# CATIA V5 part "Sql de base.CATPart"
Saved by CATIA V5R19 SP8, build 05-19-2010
Part number: Sql de base
Publications: "Origine", "A bielle", "B bielle", "Longueur Bielle", "entraxe", "D bielle", "C bielle", "Z chape verin para", "Y chape verin para", "Z chape verin frein", "Y chape verin frein", "B verin para", "B verin frein", "A verin frein", "A verin para", "Axe sabot", "Plan xy", "Plan yz", "Plan zx", "Cremaillere", "Z cremaillere", "Largeur bielle", "X Sabot", "Y Sabot", "X Cremaillere", "Y Cremaillere"
Bounding box of the stored display mesh (mm): x 0 to 0, y -950 to 470, z -1670 to 0
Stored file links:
  G:\EU_thinkMotion\CFAO_2010\MMS_groupe3\MMS_groupe3\rdalborgo\rdalborgo\Sql de base.CATPart
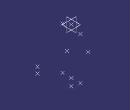
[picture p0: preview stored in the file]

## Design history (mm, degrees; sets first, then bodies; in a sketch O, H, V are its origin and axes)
Parameters
  entraxe = 500 mm
  `Longueur Bielle` = 1200 mm
  `Z chape verin para` = -425 mm
  `Y chape verin para` = 470 mm
  `Z chape verin frein` = -1500 mm {= -`Longueur Bielle` -300mm}
  `Y chape verin frein` = -950 mm
  `Z cremaillere` = -1670 mm {= `Z chape verin frein` -170mm}
  `Largeur bielle` = 210 mm
  `X Sabot` = 270 mm {= `Largeur bielle` +60mm}
  `Y Sabot` = 200 mm
  `X Cremaillere` = 330 mm {= `X Sabot` +60mm}
  `Y Cremaillere` = 230 mm {= `Y Sabot` +30mm}
Set1
  Point1 "Origine": (0, 0, 0)
  Point2 "A bielle": (0, -250 {= -entraxe /2}, -100)
  Point3 "B bielle": (0, 250 {= entraxe /2}, -100)
  Point4 "C bielle": (0, 0, -1200 {= -`Longueur Bielle`}), relative to Point3
  Point5 "D bielle": (0, -500 {= -entraxe}, 0), relative to Point4
  Point6 "A verin para": (0, 470 {= `Y chape verin para`}, -425 {= `Z chape verin para`})
  Point7 "A verin frein": (0, -950 {= `Y chape verin frein`}, -1500 {= `Z chape verin frein`}), relative to Point1
  Point8 "B verin para": (0, 130, -600 {= -`Longueur Bielle`  /2}), relative to Point2
  Point9 "B verin frein": (0, 0, -1500 {= `Z chape verin frein`}), relative to Point1
  Point10 "Axe sabot": (0, -250 {= -entraxe /2}, 0), relative to Point4
  Point11 "Cremaillere": (0, -950 {= `Y chape verin frein`}, -1670 {= `Z cremaillere`}), relative to Point1
Body1 (main body)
